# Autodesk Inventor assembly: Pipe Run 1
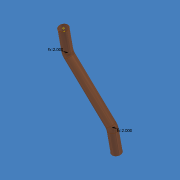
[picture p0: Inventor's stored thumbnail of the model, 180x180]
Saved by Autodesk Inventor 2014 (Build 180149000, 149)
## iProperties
Company: Autodesk, Inc.
Control State: 0
Master: False
Checked Out: False
Part Number: Pipe Run 1
Document SubType Name: Tube & Pipe
Created: 2003-10
Designer: Autodesk, Inc.
Manufacturer: Standard
Standards Organization: Custom
Mass: 1828.05 g
Surface Area: 2305.95 cm^2
Volume: 204.48 cm^3
Density: 8.94 g/cm^3
Name: Large Copper Tubing
ActiveState: True
PipeType: Tubing
Material: UnInitValue
Standard: UnInitValue
FittingMaterial: UnInitValue
FittingStandard: UnInitValue
RouteDirection90: True
RouteDirection45: False
DiameterType: Nominal
Diameter: 2
Schedule: L
OD: UnInitValue
ID: UnInitValue
Ending: UnInitValue
IntermediateSegmentsMin: 0.000 in
IntermediateSegmentsMax: 100.000 in
IntermediateSegmentsInc: 0.100 in
TerminationSegmentsMin: 0.000 in
TerminationSegmentsMax: 100.000 in
TerminationSegmentsInc: 0.100 in
DefaultBendRadius: 2.000 in
PipingComponentColor: As Material
PipeKey: V3#44B182C9-4BCE-4825-BB4D-596143122252#24
CouplingKey: V3#0DC1AE02-7BBF-4CCF-8498-581434B0A765#8
Elbow90Key: UnInitValue
Elbow45Key: UnInitValue
BendRadius: UnInitValue
EndFittingKey: UnInitValue
FlangeKey: UnInitValue
Gap: UnInitValue
GasketKey: UnInitValue
IsButtWelded: UnInitValue
IsFlanged: UnInitValue
MixedUnits: UnInitValue
RoundUpValue: UnInitValue
ShowGap: UnInitValue
StartFittingKey: UnInitValue
SuppressEndFitting: UnInitValue
SuppressStartFitting: UnInitValue
UseFlangsForCouplings: UnInitValue
UseSubASM: UnInitValue
_ComponentInfo: <CS><C N="Pipe" R="2.698750" OR="2.698750" IR="2.520950" PL="PL" PartType="pipe" SymKey="" PN="ASTM B 88 Tube 2 - Type L"><CO N="1"><FE V="0"/><FD V="0"/><ET V=
Shininess: 64.0
Length Units: 11272
Angle Units: 11279
Time Units: 11290
Mass Units: 11286
Length Display Precision: 3
Angle Display Precision: 2
Compacted: True
TPVersion: 11.0.2
Density: 0.0
Volumn: 0.0
Area: 0.0
PropertySet Name: Model Information
Author: Autodesk, Inc.
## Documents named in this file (3)
- C:\Users\iTools\Desktop\tutorial files\Tube and Pipe\Accumulator\AIP\Run1\Tube Run1.iam
- C:\Users\iTools\Desktop\tutorial files\Tube and Pipe\Accumulator\AIP\Run1\piroute.1067628982263.ipt
- C:\Users\iTools\Desktop\tutorial files\Tube and Pipe\Accumulator\AIP\Run1\pisweep.1173803379834.ipt
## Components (2 placed, 2 different names)
1. Pipe Route
2. Tube Segment 3:1
